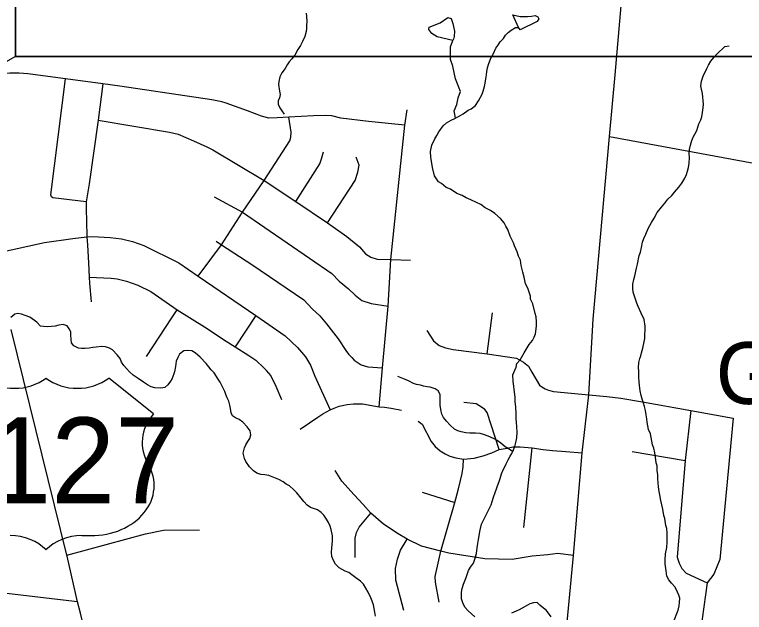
# Model space of a CAD drawing. Extents: x 0 to 34, y 0 to 22.
# Drawn here: x 5.853 to 6.973, y 18.558 to 19.475 of the extents above; entities that cross this region are included whole.
import ezdxf

# ---------------------------------------------------------------- set-up
doc = ezdxf.new("R2010")
doc.units = 0
for name, color, linetype in [('GM_X_City_Street', 7, 'Continuous'), ('GM_X_Corporation_Text', 7, 'Continuous'), ('GM_X_County_Road', 7, 'Continuous'), ('GM_X_Minor_Lake', 7, 'Continuous'), ('GM_X_Minor_River', 7, 'Continuous'), ('GM_X_Township_Subdivision', 7, 'Continuous'), ('GM_X_US_Location', 7, 'Continuous'), ('GM_X_US_Route', 7, 'Continuous'), ('GM_X_US_Shield', 7, 'Continuous'), ('RD_P_Text', 7, 'Continuous'), ('SH_Masking', 7, 'Continuous')]:
    doc.layers.add(name, color=color, linetype=linetype)

msp = doc.modelspace()

# ---------------------------------------------------------------- linework, layer by layer
at = {"layer": 'GM_X_City_Street'}
for points in [[(6.7405, 19.0079), (6.7405, 19.0079), (6.7657, 19.288), (6.7742, 19.3827), (6.7997, 19.6706), (6.8028, 19.7088), (6.8332, 20.0742), (6.8703, 20.5257), (6.8776, 20.6185)], [(6.7657, 19.288), (7.1613, 19.2149), (7.265, 19.1946), (7.3185, 19.1843), (7.7448, 19.0962), (7.7625, 19.0934), (7.7731, 19.0923), (7.7798, 19.0928), (7.9442, 19.1116)]]:
    msp.add_lwpolyline(points, dxfattribs=at)
at = {"layer": 'GM_X_County_Road'}
msp.add_lwpolyline([(6.6289, 17.5702), (6.6299, 17.6523), (6.6319, 17.6948), (6.6451, 17.8156), (6.6585, 17.9713), (6.6613, 18.0126), (6.6624, 18.0856), (6.6748, 18.2683), (6.7103, 18.6453), (6.7239, 18.8027), (6.734, 18.8917), (6.7405, 19.0079)], dxfattribs=at)
at = {"layer": 'GM_X_Minor_Lake'}
msp.add_line((6.6286, 19.4514), (6.6262, 19.4552), dxfattribs=at)
for points in [[(6.5256, 19.4351), (6.5015, 19.4405), (6.4933, 19.4457), (6.4889, 19.4522), (6.4893, 19.4556), (6.5062, 19.4621), (6.5177, 19.4706), (6.523, 19.469)], [(6.523, 19.469), (6.5255, 19.461), (6.5279, 19.4495), (6.5274, 19.4415), (6.5266, 19.4374), (6.5256, 19.4351)], [(6.6262, 19.4552), (6.6177, 19.4743), (6.6287, 19.4721), (6.6401, 19.4719), (6.6462, 19.4725), (6.6515, 19.4732), (6.6557, 19.4716), (6.6571, 19.4681), (6.6548, 19.464)], [(6.6548, 19.464), (6.6286, 19.4514)]]:
    msp.add_lwpolyline(points, dxfattribs=at)
at = {"layer": 'GM_X_Minor_River'}
for points in [[(6.3006, 19.477), (6.3012, 19.4724), (6.3014, 19.4636), (6.3013, 19.4591), (6.3008, 19.4534), (6.3004, 19.4488), (6.2987, 19.4413), (6.2947, 19.4337), (6.2916, 19.4277), (6.288, 19.4213), (6.2829, 19.4127), (6.2786, 19.4071), (6.2747, 19.4022), (6.2712, 19.3977), (6.2681, 19.392), (6.263, 19.3853), (6.2602, 19.3793), (6.2586, 19.3721), (6.2581, 19.3675), (6.2594, 19.3576), (6.2608, 19.3523), (6.2596, 19.3473), (6.2576, 19.3428), (6.2575, 19.3375), (6.26, 19.3317), (6.2634, 19.3271), (6.2667, 19.3221)], [(6.6237, 18.9396), (6.6288, 18.9455), (6.6347, 18.9561), (6.6425, 18.9688), (6.6476, 18.9748), (6.6503, 18.9801), (6.652, 18.9854), (6.6537, 18.9968), (6.6538, 19.0036), (6.6532, 19.0112), (6.6518, 19.0166), (6.6483, 19.0311), (6.6447, 19.0384), (6.6444, 19.043), (6.6405, 19.0552), (6.6368, 19.0618), (6.6347, 19.0721), (6.633, 19.0801), (6.6302, 19.09), (6.6292, 19.0981), (6.6263, 19.1046), (6.6241, 19.1111), (6.6202, 19.1203), (6.6184, 19.1249), (6.6136, 19.1353), (6.6097, 19.1452), (6.6067, 19.1502), (6.6042, 19.1556), (6.5986, 19.1622), (6.59, 19.1696), (6.5833, 19.1743), (6.575, 19.1786), (6.5683, 19.1837), (6.5615, 19.1869), (6.5533, 19.1909), (6.5457, 19.1937), (6.5397, 19.1972), (6.5314, 19.2004), (6.5217, 19.2071), (6.5153, 19.2099), (6.5082, 19.2157), (6.5033, 19.2185), (6.4971, 19.2277), (6.4943, 19.2403), (6.4919, 19.256), (6.4914, 19.2651), (6.4935, 19.2746), (6.4978, 19.2844), (6.501, 19.2896), (6.5041, 19.2953), (6.5104, 19.3043), (6.5158, 19.3087), (6.5227, 19.3128), (6.5285, 19.3157), (6.5342, 19.3186), (6.5411, 19.3227), (6.5488, 19.3282), (6.5534, 19.3304), (6.56, 19.3356), (6.5647, 19.3424), (6.5702, 19.3529), (6.5718, 19.3574), (6.5742, 19.3646), (6.5751, 19.3696), (6.576, 19.3764), (6.5769, 19.3824), (6.5777, 19.3874), (6.5786, 19.3931), (6.5802, 19.3984), (6.5835, 19.4082), (6.5878, 19.4153), (6.5914, 19.4232), (6.5945, 19.4277), (6.598, 19.433), (6.6031, 19.4382), (6.6062, 19.4431), (6.6101, 19.4476), (6.6147, 19.4509), (6.6216, 19.455), (6.6262, 19.4552)], [(6.5293, 19.3162), (6.5276, 19.3275), (6.5315, 19.3372), (6.5335, 19.347), (6.5374, 19.3568), (6.5296, 19.3764), (6.5256, 19.396), (6.5217, 19.4058), (6.5217, 19.4253), (6.5256, 19.4351)], [(6.8885, 19.2682), (6.8898, 19.2746), (6.8918, 19.2818), (6.8942, 19.2871), (6.8966, 19.2916), (6.8997, 19.2973), (6.9029, 19.3071), (6.9057, 19.3135), (6.9073, 19.318), (6.9082, 19.3245), (6.9095, 19.3317), (6.91, 19.3374), (6.9085, 19.3537), (6.9067, 19.3606), (6.906, 19.3656), (6.9066, 19.3728), (6.9098, 19.3819), (6.9122, 19.3868), (6.9149, 19.392), (6.9177, 19.3973), (6.9212, 19.4033), (6.9259, 19.4089), (6.9309, 19.4145), (6.9426, 19.4257), (6.9494, 19.4271)], [(6.8636, 18.5422), (6.8711, 18.5615), (6.8728, 18.5683), (6.8732, 18.5732), (6.8734, 18.5797), (6.872, 18.5847), (6.8698, 18.5893), (6.8665, 18.5966), (6.8606, 18.6028), (6.8569, 18.6082), (6.8536, 18.6139), (6.8526, 18.622), (6.8509, 18.6326), (6.851, 18.638), (6.8516, 18.6478), (6.8537, 18.6577), (6.8542, 18.6657), (6.8544, 18.6725), (6.8542, 18.6797), (6.8535, 18.6866), (6.8521, 18.6916), (6.8504, 18.7023), (6.849, 18.7068), (6.8473, 18.7164), (6.8459, 18.7229), (6.8445, 18.7298), (6.8428, 18.7382), (6.8418, 18.7435), (6.8408, 18.7504), (6.8402, 18.7568), (6.8399, 18.7629), (6.8397, 18.7694), (6.839, 18.7751), (6.8388, 18.7827), (6.8374, 18.7877), (6.8364, 18.7961), (6.835, 18.8026), (6.8336, 18.8098), (6.8319, 18.8152), (6.8284, 18.832), (6.8255, 18.8385), (6.8245, 18.8443), (6.8234, 18.8496), (6.8228, 18.8549), (6.8218, 18.861), (6.8208, 18.8675), (6.8194, 18.8736), (6.818, 18.879), (6.8165, 18.8836), (6.8144, 18.8909), (6.813, 18.8977), (6.8117, 18.9061), (6.8114, 18.9115), (6.8108, 18.9187), (6.8106, 18.9286), (6.8103, 18.9332), (6.8105, 18.9411), (6.8121, 18.9472), (6.8137, 18.9517), (6.815, 18.9563), (6.8166, 18.9631), (6.8191, 18.9729), (6.82, 18.9782), (6.8204, 18.9972), (6.8187, 19.0072), (6.8143, 19.0171), (6.8096, 19.0271), (6.8078, 19.0321), (6.8042, 19.0432), (6.8021, 19.0493), (6.8014, 19.0547), (6.8015, 19.0615), (6.8028, 19.0687), (6.8048, 19.074), (6.807, 19.0861), (6.8086, 19.0922), (6.8112, 19.1054), (6.8132, 19.1103), (6.8148, 19.1175), (6.8165, 19.1259), (6.8185, 19.1315), (6.8213, 19.1383), (6.8249, 19.147), (6.83, 19.156), (6.8344, 19.1628), (6.8387, 19.1711), (6.8453, 19.1797), (6.8504, 19.1857), (6.8554, 19.192), (6.8612, 19.1976), (6.8655, 19.2025), (6.8718, 19.21), (6.8768, 19.2163), (6.8815, 19.2242), (6.8839, 19.2295), (6.8855, 19.2348), (6.8868, 19.2405), (6.8877, 19.2469), (6.8882, 19.2553), (6.888, 19.2625), (6.8885, 19.2682)], [(6.1551, 18.9299), (6.1514, 18.9345), (6.1473, 18.9396), (6.138, 18.9493), (6.1302, 18.9559), (6.1253, 18.959), (6.1189, 18.9599), (6.1128, 18.9593), (6.1062, 18.9541), (6.1038, 18.9488), (6.1014, 18.9432), (6.1002, 18.9352), (6.0985, 18.9272), (6.0948, 18.917), (6.0925, 18.9125), (6.0886, 18.9069), (6.0839, 18.9032), (6.0778, 18.9022), (6.0687, 18.9027), (6.0627, 18.904), (6.0571, 18.9071), (6.0511, 18.9111), (6.0428, 18.9169), (6.0354, 18.922), (6.0294, 18.9271), (6.0249, 18.9321), (6.0208, 18.9368), (6.0172, 18.9418), (6.0154, 18.9472), (6.0109, 18.9529), (6.0035, 18.9607), (5.999, 18.9631), (5.993, 18.9655), (5.9873, 18.966), (5.9785, 18.965), (5.9736, 18.9643), (5.9679, 18.9633), (5.961, 18.9627), (5.9561, 18.9628), (5.9515, 18.9633), (5.944, 18.9668), (5.9407, 18.9715), (5.94, 18.9764), (5.9398, 18.9837), (5.9395, 18.9882), (5.9373, 18.9932), (5.934, 18.9978), (5.928, 18.9995), (5.9211, 18.9985), (5.9154, 18.9971), (5.9101, 18.9964), (5.9032, 18.9962), (5.8979, 18.9963), (5.893, 18.9971), (5.8874, 19.003), (5.877, 19.0108), (5.8698, 19.0136), (5.8642, 19.0156), (5.8581, 19.0165), (5.8535, 19.0154), (5.8477, 19.0102)], [(6.5593, 18.5514), (6.5492, 18.5603), (6.5444, 18.5658), (6.5411, 18.5711), (6.5386, 18.5788), (6.5388, 18.5891), (6.54, 18.5947), (6.5417, 18.6012), (6.5457, 18.6117), (6.5493, 18.6223), (6.5524, 18.6272), (6.5571, 18.6336), (6.5596, 18.6415), (6.5616, 18.6483), (6.5629, 18.657), (6.5638, 18.6639), (6.5647, 18.6699), (6.5656, 18.6756), (6.5668, 18.6821), (6.5681, 18.6866), (6.5694, 18.6934), (6.5737, 18.7017), (6.5769, 18.7089), (6.5816, 18.7179), (6.584, 18.7228), (6.586, 18.7281), (6.588, 18.7349), (6.5905, 18.7421), (6.5925, 18.7474), (6.5941, 18.7523), (6.5965, 18.7587), (6.5981, 18.7632), (6.6002, 18.7708), (6.6029, 18.7768), (6.6053, 18.7813), (6.6073, 18.7859), (6.6101, 18.7919), (6.6132, 18.7975), (6.616, 18.802), (6.6184, 18.8073), (6.6204, 18.8126), (6.6224, 18.8209), (6.6237, 18.8258), (6.6242, 18.8346), (6.6236, 18.8426), (6.623, 18.8498), (6.6227, 18.8544), (6.6225, 18.8631), (6.622, 18.8727), (6.621, 18.8814), (6.6208, 18.8879), (6.6195, 18.9001), (6.6188, 18.905), (6.6178, 18.9123), (6.6177, 18.9226), (6.6205, 18.9294), (6.6228, 18.9343), (6.6237, 18.9396)], [(6.4071, 18.5521), (6.4057, 18.5583), (6.405, 18.564), (6.4036, 18.5697), (6.4018, 18.5751), (6.3997, 18.5804), (6.3957, 18.5889), (6.392, 18.5954), (6.3883, 18.6016), (6.3839, 18.6059), (6.3768, 18.6113), (6.3704, 18.6156), (6.3659, 18.6195), (6.3606, 18.6215), (6.3509, 18.6263), (6.3457, 18.6321), (6.3424, 18.6379), (6.3398, 18.644), (6.3392, 18.6497), (6.3397, 18.6569), (6.3402, 18.6615), (6.3411, 18.6683), (6.3409, 18.6756), (6.3388, 18.6851), (6.3374, 18.6901), (6.3348, 18.6958), (6.3315, 18.7012), (6.3278, 18.707), (6.3234, 18.7113), (6.3178, 18.7156), (6.3117, 18.7176), (6.3072, 18.7192), (6.302, 18.7227), (6.2971, 18.7282), (6.2927, 18.7332), (6.286, 18.7417), (6.2816, 18.7463), (6.2748, 18.7522), (6.27, 18.7549), (6.2651, 18.7581), (6.2587, 18.762), (6.2512, 18.7652), (6.2433, 18.768), (6.2369, 18.7693), (6.2308, 18.7698), (6.2251, 18.7714), (6.2199, 18.775), (6.2136, 18.7812), (6.208, 18.7893), (6.2058, 18.7939), (6.2041, 18.8023), (6.2058, 18.8106), (6.2082, 18.8151), (6.2113, 18.8204), (6.2141, 18.8249), (6.2157, 18.8306), (6.2147, 18.8363), (6.2103, 18.8429), (6.2036, 18.8498), (6.198, 18.8537), (6.1923, 18.8565), (6.1878, 18.8593), (6.1856, 18.8643), (6.1846, 18.8707), (6.1836, 18.8761), (6.1818, 18.8818), (6.1793, 18.8872), (6.1775, 18.8922), (6.1757, 18.8968), (6.1713, 18.906), (6.1684, 18.911), (6.1658, 18.916), (6.1592, 18.9253), (6.1551, 18.9299)], [(6.6173, 18.8049), (6.6059, 18.8121), (6.5992, 18.8176), (6.5936, 18.8219), (6.5876, 18.825), (6.5797, 18.8286), (6.5725, 18.8307), (6.5672, 18.8323), (6.5604, 18.8332), (6.5517, 18.833), (6.5452, 18.8335), (6.5384, 18.8348), (6.5332, 18.8364), (6.5279, 18.8392), (6.5212, 18.845), (6.516, 18.8512), (6.5112, 18.857), (6.5086, 18.862), (6.5069, 18.8693), (6.5062, 18.8757), (6.506, 18.8822), (6.5061, 18.8868), (6.5058, 18.8921), (6.5029, 18.8979), (6.4984, 18.901), (6.4909, 18.9034), (6.4859, 18.9039), (6.4807, 18.9051), (6.4757, 18.9064), (6.4697, 18.9076), (6.4652, 18.9093), (6.4577, 18.9132), (6.4513, 18.916), (6.4464, 18.9176), (6.4411, 18.92)], [(6.6762, 18.5513), (6.6692, 18.561), (6.6643, 18.5645), (6.6591, 18.5692), (6.6546, 18.5731), (6.6493, 18.5728), (6.6436, 18.5714), (6.6366, 18.5673), (6.6274, 18.5622), (6.6224, 18.56), (6.6155, 18.5567)]]:
    msp.add_lwpolyline(points, dxfattribs=at)
at = {"layer": 'GM_X_Township_Subdivision'}
for points in [[(6.4519, 19.3054), (6.396, 19.3109), (6.3537, 19.316), (6.3398, 19.3194), (6.33, 19.3201), (6.3118, 19.3195), (6.2741, 19.3176), (6.256, 19.3166), (6.2434, 19.3159), (6.2321, 19.3189), (6.2106, 19.3271), (6.1778, 19.3388), (6.171, 19.3409), (6.156, 19.344), (6.0148, 19.3653), (5.9886, 19.3688), (5.9313, 19.3764), (5.8736, 19.384), (5.8604, 19.3848), (5.846, 19.3852), (5.8274, 19.3843), (5.8043, 19.3821), (5.7557, 19.3719)], [(5.9633, 19.1876), (5.9122, 19.1937), (5.91, 19.1952), (5.9089, 19.1983), (5.9313, 19.3764)], [(5.9886, 19.3688), (5.9815, 19.3127), (5.9679, 19.2152), (5.9633, 19.1876), (5.963, 19.1759), (5.9637, 19.1585), (5.9642, 19.1338), (5.965, 19.1213), (5.9668, 19.094), (5.9677, 19.0721), (5.9681, 19.0632), (5.9707, 19.0342)], [(6.4123, 18.8733), (6.4176, 18.933), (6.4265, 19.0277), (6.4303, 19.0992), (6.4519, 19.3054), (6.4556, 19.3289)], [(5.9815, 19.3127), (6.0911, 19.2943), (6.1043, 19.2916), (6.1275, 19.2814), (6.1481, 19.272), (6.1574, 19.2672), (6.236, 19.2202), (6.2849, 19.188), (6.3334, 19.1553), (6.3629, 19.1343), (6.3822, 19.1187), (6.3914, 19.1078), (6.3999, 19.1029), (6.4093, 19.1), (6.4303, 19.0992), (6.4605, 19.0981)], [(6.1351, 19.0738), (6.1707, 19.1218), (6.203, 19.1719), (6.236, 19.2202), (6.2753, 19.2811), (6.277, 19.2871), (6.2773, 19.2943), (6.2741, 19.3176)], [(6.2849, 19.188), (6.3217, 19.2458), (6.3242, 19.2535), (6.3272, 19.2642)], [(6.3334, 19.1553), (6.3757, 19.2204), (6.38, 19.2331), (6.3818, 19.2441), (6.3773, 19.2564)], [(6.1594, 19.1953), (6.203, 19.1719), (6.3397, 19.0779), (6.3513, 19.0663), (6.3654, 19.0543), (6.3756, 19.0448), (6.3858, 19.0365), (6.4001, 19.0319), (6.4265, 19.0277)], [(5.8219, 19.1086), (5.8995, 19.1253), (5.9425, 19.1316), (5.9642, 19.1338), (5.9731, 19.1343), (6, 19.133), (6.0174, 19.1311), (6.0343, 19.1268), (6.0514, 19.1209), (6.1052, 19.0944), (6.1351, 19.0738), (6.2232, 19.0134), (6.2685, 18.9823), (6.2873, 18.9643), (6.2994, 18.9498), (6.3074, 18.9374), (6.3136, 18.9202), (6.3373, 18.8686)], [(6.1624, 19.1272), (6.1707, 19.1218), (6.217, 19.0915), (6.297, 19.0372), (6.3096, 19.0236), (6.3213, 19.0128), (6.3316, 19.0008), (6.3494, 18.9776), (6.3623, 18.9581), (6.3662, 18.9534), (6.3706, 18.9491), (6.3743, 18.9447), (6.3849, 18.9375), (6.3952, 18.9346), (6.4176, 18.933)], [(5.9677, 19.0721), (6.0013, 19.0707), (6.0108, 19.0695), (6.025, 19.0663), (6.0423, 19.06), (6.0623, 19.05), (6.1029, 19.0223), (6.1446, 18.9959), (6.1781, 18.974), (6.1915, 18.9655), (6.2127, 18.9521), (6.2231, 18.9449), (6.2363, 18.9324), (6.2391, 18.9294), (6.2393, 18.929)], [(6.0557, 18.9504), (6.0946, 19.01), (6.1029, 19.0223)], [(6.5779, 18.9545), (6.5861, 19.0175)], [(6.2232, 19.0134), (6.1915, 18.9655)], [(6.4855, 18.9903), (6.496, 18.9745), (6.5043, 18.9675), (6.5141, 18.9637), (6.5258, 18.9615), (6.5779, 18.9545), (6.6233, 18.9478), (6.634, 18.942), (6.6413, 18.9357), (6.6468, 18.9265), (6.6586, 18.9068), (6.6621, 18.9039), (6.6673, 18.9009), (6.672, 18.8989), (6.6796, 18.8967), (6.734, 18.8917), (6.7616, 18.8893), (6.7833, 18.8868), (6.8164, 18.8809), (6.8904, 18.8675), (6.9555, 18.8557)], [(6.2393, 18.929), (6.2466, 18.921), (6.2541, 18.9052), (6.2629, 18.8848)], [(6.2915, 18.8391), (6.3058, 18.8487), (6.3184, 18.8577), (6.3259, 18.8627), (6.3373, 18.8686), (6.3434, 18.8713), (6.3513, 18.8746), (6.3636, 18.877), (6.3733, 18.8781), (6.3868, 18.8778), (6.4123, 18.8733), (6.4208, 18.8726), (6.4311, 18.8711), (6.4467, 18.8684)], [(6.5967, 18.8078), (6.5781, 18.8647), (6.5744, 18.869), (6.5696, 18.8729), (6.561, 18.8781), (6.5421, 18.8802)], [(6.8904, 18.8675), (6.8817, 18.7908), (6.8694, 18.6429), (6.8725, 18.6335), (6.8766, 18.6254), (6.8834, 18.6184), (6.9157, 18.6034)], [(6.4725, 18.8515), (6.4783, 18.8466), (6.4924, 18.8202), (6.4985, 18.8125), (6.5061, 18.806), (6.5136, 18.801), (6.5208, 18.7976), (6.5302, 18.7949), (6.5417, 18.7929), (6.5582, 18.7944), (6.572, 18.7983), (6.5851, 18.803), (6.5967, 18.8078), (6.6087, 18.8102), (6.6176, 18.8122), (6.6289, 18.8119), (6.6469, 18.8103), (6.6639, 18.8078), (6.6785, 18.8064), (6.6989, 18.8047), (6.7239, 18.8027)], [(6.9555, 18.8557), (6.9347, 18.639), (6.9257, 18.6167), (6.9157, 18.6034), (6.9052, 18.5296)], [(6.6345, 18.6882), (6.6469, 18.8103)], [(6.8004, 18.8047), (6.8817, 18.7908)], [(6.5044, 18.5736), (6.4989, 18.6042), (6.4984, 18.6133), (6.5019, 18.6291), (6.5071, 18.652), (6.5287, 18.7268), (6.5337, 18.7456), (6.5371, 18.7603), (6.54, 18.7712), (6.5415, 18.7812), (6.5417, 18.7929)], [(6.7103, 18.6453), (6.6863, 18.6486), (6.6711, 18.6464), (6.6472, 18.6445), (6.6167, 18.6394), (6.5746, 18.6402), (6.5192, 18.6488), (6.5071, 18.652), (6.4774, 18.6599), (6.4556, 18.6705), (6.4416, 18.6785), (6.4193, 18.6934), (6.3997, 18.7104), (6.388, 18.7238), (6.3744, 18.7385), (6.3552, 18.7594), (6.345, 18.7756)], [(6.4782, 18.7425), (6.5287, 18.7268)], [(6.3757, 18.6425), (6.3755, 18.6721), (6.3776, 18.6808), (6.3817, 18.689), (6.3997, 18.7104)], [(5.9336, 18.646), (6.0543, 18.6784), (6.0815, 18.6843), (6.1368, 18.6847)], [(6.4502, 18.5612), (6.4383, 18.6075), (6.4377, 18.6254), (6.4404, 18.6397), (6.4454, 18.6533), (6.4556, 18.6705)], [(5.9496, 18.5742), (5.6318, 18.6117)]]:
    msp.add_lwpolyline(points, dxfattribs=at)
at = {"layer": 'GM_X_US_Route'}
for points in [[(5.934, 18.6441), (5.9336, 18.646), (5.8479, 18.9921)], [(5.9806, 18.449), (5.9547, 18.5569), (5.9496, 18.5742), (5.934, 18.6441)]]:
    msp.add_lwpolyline(points, dxfattribs=at)
at = {"layer": 'GM_X_US_Shield'}
for p, q in [((6.0663, 18.8626), (5.9977, 18.9175)), ((5.9565, 18.6758), (5.9702, 18.6758))]:
    msp.add_line(p, q, dxfattribs=at)
for centre, major_axis, start_param, end_param in [((5.8535, 18.9567), (-0.0687, 0), 0.795399, 2.346194), ((5.9496, 18.9567), (-0.0687, 0), 0.795399, 2.346194), ((6.1451, 18.8184), (-0.0961, 0), 5.672304, 6.727422), ((5.9713, 18.7527), (-0.0961, 0), 1.559657, 3.580859), ((5.8466, 18.6209), (-0.0687, 0), 3.785094, 4.712389), ((5.9565, 18.6209), (-0.0687, 0), 4.712389, 5.639684)]:
    msp.add_ellipse(centre, major_axis=major_axis, ratio=0.8, start_param=start_param, end_param=end_param, dxfattribs=at)
at = {"layer": 'RD_P_Text'}
msp.add_lwpolyline([(5.8549, 19.8788), (7.7843, 19.8788), (7.7843, 19.4106), (5.8549, 19.4106)], close=True, dxfattribs=at)
msp.add_lwpolyline([(5.8549, 19.4106), (5.2002, 19.0384), (5.8549, 19.5598), (5.8549, 19.4106)], dxfattribs=at)
at = {"layer": 'SH_Masking'}
msp.add_lwpolyline([(7.7843, 19.8788), (5.8549, 19.8788), (5.8549, 19.4106), (7.7843, 19.4106)], close=True, dxfattribs=at)

# ---------------------------------------------------------------- texts
at = {"layer": 'GM_X_Corporation_Text'}
msp.add_text('GREENHILLS', height=0.0947, rotation=0, dxfattribs=at).set_placement((6.9287, 18.8777))
at = {"layer": 'GM_X_US_Location'}
for s in ['0', '/']:
    msp.add_text(s, height=0.000189, dxfattribs=at).set_placement((5.9016, 18.791))
at = {"layer": 'GM_X_US_Shield'}
msp.add_text('127', height=0.13184, dxfattribs=at).set_placement((5.8115, 18.7252))

doc.saveas('drawing.dxf')
